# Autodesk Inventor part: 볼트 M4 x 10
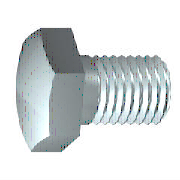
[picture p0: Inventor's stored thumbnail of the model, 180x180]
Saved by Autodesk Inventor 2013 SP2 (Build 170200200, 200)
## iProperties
Created: 2012-02
Part Number: 볼트 M4 x 10
Material: 스테인리스강
Description: 6각 머리 나사
Document SubType Name: Modeling
Standard: ISO 4017
Designer: mduedu
Standard Revision: Third edition 1999-08-15
Standards Organization: ISO
Language: ko-KR
Size Designation: M4 x 10
Categories: <MemberInstance><Categories><Category DisplayName="조임쇠" InternalName="e4da775c-781d-43d5-af7c-5136215cf5a6" Mnemonic="FSTN"><Category DisplayName="볼트" InternalN
Density: 8.08 g/cm^3
Mass: 1.91889 g
Surface Area: 2.7092 cm^2
Volume: 0.237486 cm^3
IsCustomPart: 0
Author: mduedu
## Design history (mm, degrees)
sketch "스케치1"
  geometry: L1 (0, 3.015)-(0, 2); L2 (2.1, 2)-(10, 2); L3 (10, 2)-(10, 0); L4 (10, 0)-(-0.4, 0); L5 (-2.48, 0)-(12.08, 0) reference; L6 (-0.4, 0)-(-0.4, 3.015); L7 (-0.4, 3.015)-(0, 3.015); L8 (2.1, 2)-(1.67, 2); L9 (1.67, 2)-(0, 2); L10 (0, -0.603)-(0, 3.618) reference
  constraints: 16 end point, 2 collinear, 2 perpendicular, 1 parallel
  dimensions: "d0" = 10 distance between parallel lines of L3 L1 (= NLG); "d1" = 7.9 distance from line of L2.start L3 (= GEL); "d2" = 4 diameter of L2 L4 (= GD); "d9" = 0.4001 distance between parallel lines of L6 L1 (computed from SD); "d10" = 6.03 diameter of L7 L4 (= SD2); "d13" = 0.42952 distance of L2.start L8.end (computed from GAL); "d14" = 4 diameter of L9 L4 (= BDM)
revolve "본체" sketch "스케치1" stored, may be unused: angle "d12" = 90 deg
sketch "스케치2"
  geometry: L1 (0, 4.041)-(3.5, 2.021); L2 (3.5, 2.021)-(3.5, -2.021); L3 (3.5, -2.021)-(0, -4.041); L4 (0, -4.041)-(-3.5, -2.021); L5 (-3.5, -2.021)-(-3.5, 2.021); L6 (-3.5, 2.021)-(0, 4.041); 2 further points
  constraints: 12 end point, 1 coincident, 1 vertical, 11 other
  dimensions: "d11" = 7 distance between parallel lines of L5 L2 (= SW)
extrude "머리" join sketch "스케치2" distance "d3" = 2.4 (= KOH - SD); taper "d4" = 0 deg
sketch "스케치4"
  geometry: L1 (-2.8, 3.5)-(-2.8, 4.041); L2 (-2.8, 4.041)-(-2.487, 4.041); L3 (-2.487, 4.041)-(-2.8, 3.5); L4 (-3.28, 0)-(0.08, 0) reference; L5 (-0.4, 4.041)-(-2.8, 4.041) reference; L6 (-2.8, 2.021)-(-2.8, 4.041) reference
  constraints: 6 end point, 2 collinear, 1 perpendicular, 1 vertical
  dimensions: "d5" = 30 deg angle of L3 L1 (= ANG1); "d19" = 7 diameter of L1.start L4 (= SW0)
revolve "모따기1" sketch "스케치4" stored, may be unused: angle "d21" = 90 deg
workplane "Work Plane1"
body "Solid1"
feature "스레드" dims "d15" = 7.9 (= GEL), "d16" = 0
chamfer "모따기2" distance "d6" = 0.42941 (= -0.5 x SPD + 0.5 x GD); stored, may be unused: second distance "d7" = 0.42952 (computed from GUL), angle "d55" = 45 deg
other parameters: "NLG" = 10 [user parameter; used in 1 equation term], "GD" = 4 (= NND) [user parameter; used in 2 equation terms], "BDM" = 4 (= NND) [user parameter; used in 1 equation term], "KOH" = 2.8 [user parameter; used in 1 equation term], "GEL" = 7.9 [user parameter; used in 2 equation terms], "SW" = 7 [user parameter; used in 2 equation terms], "SW0" = 7 (= SW) [user parameter; used in 1 equation term], "SPD" = 3.14117 (= NND - 1.2269 x PTC) [user parameter; used in 1 equation term], "SD2" = 6.03 [user parameter; used in 2 equation terms], "SD" = 0.4 [user parameter; used in 2 equation terms], "ANG1" = 30 deg [user parameter; used in 1 equation term], "GAL" = 0.42941 (= 0.61345 x PTC) [user parameter; used in 1 equation term], "GUL" = 0.42941 (= 0.61345 x PTC) [user parameter; used in 1 equation term], "d8" = 0, "RR" = 0.2 [user parameter], "d57" = 0, "d58" = 0, "TPU" = 14.28571 (computed from PTC) [user parameter], "GD1" = 3.14117 (= THREADDIA - 1.2269 x PTC) [user parameter], "THREADDIA" = 4 [user parameter; used in 1 equation term], "SDH" = 6.03 (= SD2) [user parameter], "SDHG" = 2.1 [user parameter], "TOA" = 30 deg [user parameter], "PTC" = 0.7 [user parameter; used in 5 equation terms], "NND" = 4 [user parameter; used in 3 equation terms], "E0" = 8.085 [user parameter]
